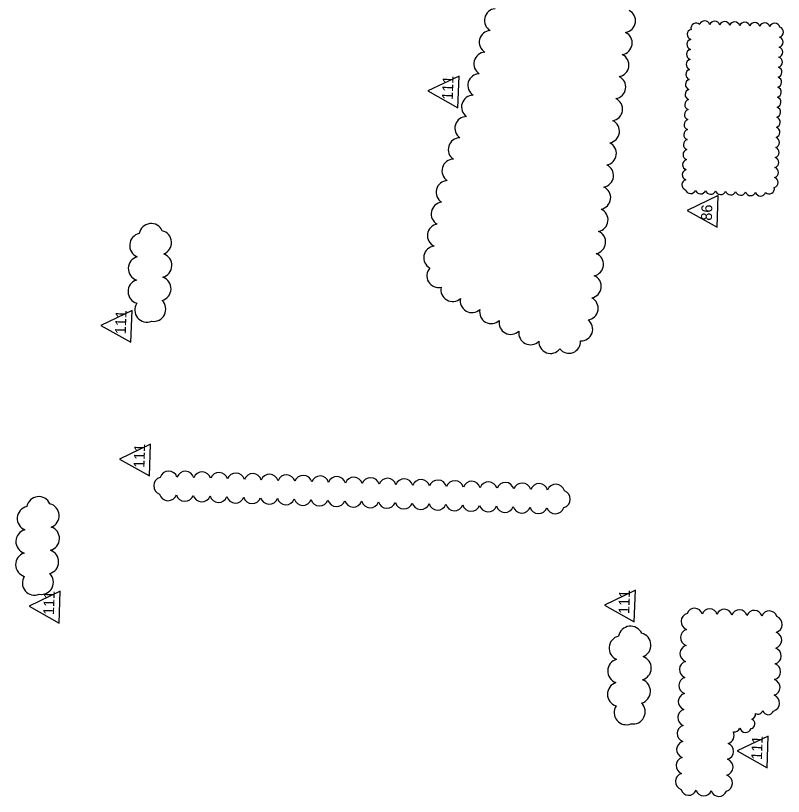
# Model space of a CAD drawing. Extents: x 928669 to 929521, y 636891 to 638153.
# Drawn here: x 928846 to 929187, y 637343.5 to 637690.4 of the extents above; entities that cross this region are included whole.
import ezdxf

# ---------------------------------------------------------------- set-up
doc = ezdxf.new("R2010")
doc.units = 0
doc.layers.add('Cloud_dp', color=7, linetype='Continuous')

msp = doc.modelspace()

# ---------------------------------------------------------------- linework, layer by layer
at = {"layer": 'Cloud_dp'}
for points in [[(929029.16, 637656.92), (929042.47, 637649.41), (929042.96, 637663.49)], [(929144.26, 637603.89), (929157.57, 637596.38), (929158.06, 637610.45)], [(928883.91, 637552.78), (928897.22, 637545.27), (928897.71, 637559.35)], [(928892.18, 637493.38), (928905.49, 637485.87), (928905.98, 637499.95)], [(928852.01, 637428.07), (928865.32, 637420.55), (928865.81, 637434.63)], [(929107.53, 637428.51), (929120.84, 637421), (929121.33, 637435.07)], [(929166.5, 637363.72), (929179.81, 637356.21), (929180.3, 637370.28)]]:
    msp.add_lwpolyline(points, close=True, dxfattribs=at)
for centre, radius, start, end in [((929059.45, 637688.27), 5.2, 94.6831, 239.6831), ((929116.19, 637688.07), 5.2, 278.7266, 63.7266), ((929148.31, 637684.8), 2.33, 47.7982, 192.7982), ((929152.08, 637685.75), 2.34, 15.4978, 160.4978), ((929156.53, 637685.59), 2.34, 15.4978, 160.4978), ((929160.99, 637685.43), 2.34, 15.4978, 160.4978), ((929165.44, 637685.28), 2.34, 15.4978, 160.4978), ((929169.89, 637685.12), 2.34, 15.4978, 160.4978), ((929174.34, 637684.97), 2.34, 15.4978, 160.4978), ((929178.79, 637684.81), 2.34, 15.4978, 160.4978), ((929183.24, 637684.66), 2.34, 15.4978, 160.4978), ((929184.71, 637683.08), 2.34, 285.4978, 70.4978), ((929057.16, 637678.6), 5.2, 93.763, 238.763), ((929114.7, 637678.26), 5.2, 278.9601, 63.9601), ((929146.66, 637682.03), 2.34, 105.4978, 250.4978), ((929146.51, 637677.58), 2.34, 105.4978, 250.4978), ((929184.56, 637678.63), 2.34, 285.4978, 70.4978), ((929146.35, 637673.13), 2.34, 105.4978, 250.4978), ((929184.4, 637674.18), 2.34, 285.4978, 70.4978), ((929054.72, 637668.97), 5.2, 92.7581, 237.7581), ((929113.24, 637668.45), 5.2, 279.1299, 64.1299), ((929184.25, 637669.73), 2.34, 285.4978, 70.4978), ((929146.2, 637668.68), 2.34, 105.4978, 250.4978), ((929052.1, 637659.38), 5.2, 91.6555, 236.6555), ((929146.04, 637664.22), 2.34, 105.4978, 250.4978), ((929184.09, 637665.28), 2.34, 285.4978, 70.4978), ((929111.81, 637658.64), 5.2, 279.2689, 64.2689), ((929145.88, 637659.77), 2.34, 105.4978, 250.4978), ((929183.93, 637660.82), 2.34, 285.4978, 70.4978), ((929145.73, 637655.32), 2.34, 105.4978, 250.4978), ((929183.78, 637656.37), 2.34, 285.4978, 70.4978), ((929049.28, 637649.85), 5.2, 90.4397, 235.4397), ((929183.62, 637651.92), 2.34, 285.4978, 70.4978), ((929110.4, 637648.83), 5.2, 279.426, 64.426), ((929145.57, 637650.87), 2.34, 105.4978, 250.4978), ((929145.42, 637646.42), 2.34, 105.4978, 250.4978), ((929183.47, 637647.47), 2.34, 285.4978, 70.4978), ((929046.32, 637640.37), 5.2, 89.8867, 234.8867), ((929109.03, 637639.01), 5.2, 279.6117, 64.6117), ((929145.26, 637641.97), 2.34, 105.4978, 250.4978), ((929183.31, 637643.02), 2.34, 285.4978, 70.4978), ((929183.16, 637638.57), 2.34, 285.4978, 70.4978), ((929145.11, 637637.52), 2.34, 105.4978, 250.4978), ((929043.39, 637630.93), 5.2, 90.5611, 235.5611), ((929107.68, 637629.19), 5.2, 279.8348, 64.8348), ((929144.95, 637633.07), 2.34, 105.4978, 250.4978), ((929183, 637634.12), 2.34, 285.4978, 70.4978), ((929144.8, 637628.62), 2.34, 105.4978, 250.4978), ((929182.84, 637629.67), 2.34, 285.4978, 70.4978), ((929040.59, 637621.45), 5.2, 91.5317, 236.5317), ((929144.64, 637624.16), 2.34, 105.4978, 250.4978), ((929182.69, 637625.21), 2.34, 285.4978, 70.4978), ((929106.39, 637619.35), 5.2, 280.11, 65.11), ((929182.53, 637620.76), 2.34, 285.4978, 70.4978), ((929144.48, 637619.71), 2.34, 105.4978, 250.4978), ((929038, 637611.92), 5.2, 93.0676, 238.0676), ((929144.33, 637615.26), 2.34, 105.4978, 250.4978), ((929182.38, 637616.31), 2.34, 285.4978, 70.4978), ((929105.14, 637609.51), 5.2, 280.4616, 65.4616), ((929145.8, 637613.69), 2.34, 195.4978, 340.4978), ((929150.25, 637613.53), 2.34, 195.4978, 340.4978), ((929154.7, 637613.37), 2.34, 195.4978, 340.4978), ((929159.15, 637613.22), 2.34, 195.4978, 340.4978), ((929163.6, 637613.06), 2.34, 195.4978, 340.4978), ((929180.73, 637613.55), 2.33, 227.7982, 12.7982), ((929168.05, 637612.91), 2.34, 195.4978, 340.4978), ((929172.51, 637612.75), 2.34, 195.4978, 340.4978), ((929176.96, 637612.6), 2.34, 195.4978, 340.4978), ((929035.8, 637602.35), 5.2, 96.0987, 241.0987), ((929103.96, 637599.66), 5.2, 280.9328, 65.9328), ((928906.22, 637592.6), 5.42, 24.5019, 169.5019), ((929034.14, 637592.67), 5.2, 99.3819, 244.3819), ((928902.08, 637588.29), 5.42, 102.6495, 247.6495), ((928909.85, 637589.58), 5.42, 291.0688, 76.0688), ((929102.89, 637589.79), 5.2, 281.6123, 66.6123), ((929032.48, 637582.83), 5.2, 96.4457, 241.4457), ((929101.94, 637579.9), 5.2, 282.473, 67.473), ((928901.48, 637578.05), 5.42, 105.565, 250.565), ((928909.99, 637579.4), 5.42, 285.576, 70.576), ((929033.87, 637574.8), 5.2, 138.1807, 283.1807), ((929100.96, 637570.08), 5.2, 281.1172, 66.1172), ((928901.36, 637567.78), 5.42, 108.172, 253.172), ((928909.64, 637569.07), 5.42, 285.4978, 70.4978), ((929040.12, 637568.62), 5.2, 167.5484, 312.5484), ((928907.29, 637559.97), 5.42, 260.4905, 45.4905), ((929048.71, 637563.67), 5.2, 167.5609, 312.5609), ((929099.58, 637560.36), 5.2, 277.71, 62.71), ((928904.35, 637559.65), 5.42, 147.1328, 292.1328), ((929057.31, 637558.77), 5.2, 168.0431, 313.0431), ((929065.95, 637553.98), 5.2, 169.0303, 314.0303), ((929097.14, 637551.07), 5.2, 267.8534, 52.8534), ((929074.69, 637549.41), 5.2, 170.7541, 315.7541), ((929083.6, 637545.52), 5.2, 176.9989, 321.9989), ((929091.76, 637545.56), 5.19, 218.5581, 3.5581), ((928913.97, 637484.12), 3.92, 18.2984, 163.2984), ((928921.39, 637484.05), 3.92, 15.4978, 160.4978), ((928928.87, 637483.79), 3.92, 15.4978, 160.4978), ((928911.26, 637481.47), 3.92, 105.4978, 250.4978), ((928936.36, 637483.52), 3.92, 15.4978, 160.4978), ((928943.84, 637483.26), 3.92, 15.4978, 160.4978), ((928951.32, 637483), 3.92, 15.4978, 160.4978), ((928958.8, 637482.74), 3.92, 15.4978, 160.4978), ((928966.28, 637482.48), 3.92, 15.4978, 160.4978), ((928973.76, 637482.22), 3.92, 15.4978, 160.4978), ((928981.24, 637481.95), 3.92, 15.4978, 160.4978), ((928988.73, 637481.69), 3.92, 15.4978, 160.4978), ((928996.21, 637481.43), 3.92, 15.4978, 160.4978), ((929003.69, 637481.17), 3.92, 15.4978, 160.4978), ((929011.17, 637480.91), 3.92, 15.4978, 160.4978), ((929018.65, 637480.65), 3.92, 15.4978, 160.4978), ((929026.13, 637480.39), 3.92, 15.4978, 160.4978), ((929033.61, 637480.12), 3.92, 15.4978, 160.4978), ((929041.1, 637479.86), 3.92, 15.4978, 160.4978), ((929048.58, 637479.6), 3.92, 15.4978, 160.4978), ((929056.06, 637479.34), 3.92, 15.4978, 160.4978), ((929063.54, 637479.08), 3.92, 15.4978, 160.4978), ((929071.02, 637478.82), 3.92, 15.4978, 160.4978), ((929078.5, 637478.55), 3.92, 15.4978, 160.4978), ((929085.98, 637478.29), 3.92, 15.4978, 160.4978), ((928913.73, 637478.82), 3.92, 195.4978, 340.4978), ((928921.21, 637478.56), 3.92, 195.4978, 340.4978), ((928928.69, 637478.3), 3.92, 195.4978, 340.4978), ((929088.46, 637475.64), 3.92, 285.4978, 70.4978), ((928856.3, 637471.27), 5.42, 24.5019, 169.5019), ((928936.17, 637478.04), 3.92, 195.4978, 340.4978), ((928943.66, 637477.77), 3.92, 195.4978, 340.4978), ((928951.14, 637477.51), 3.92, 195.4978, 340.4978), ((928958.62, 637477.25), 3.92, 195.4978, 340.4978), ((928966.1, 637476.99), 3.92, 195.4978, 340.4978), ((928973.58, 637476.73), 3.92, 195.4978, 340.4978), ((928981.06, 637476.47), 3.92, 195.4978, 340.4978), ((928988.54, 637476.2), 3.92, 195.4978, 340.4978), ((928996.03, 637475.94), 3.92, 195.4978, 340.4978), ((929003.51, 637475.68), 3.92, 195.4978, 340.4978), ((929010.99, 637475.42), 3.92, 195.4978, 340.4978), ((929018.47, 637475.16), 3.92, 195.4978, 340.4978), ((929025.95, 637474.9), 3.92, 195.4978, 340.4978), ((928852.16, 637466.97), 5.42, 102.6495, 247.6495), ((928859.92, 637468.25), 5.42, 291.0688, 76.0688), ((929033.43, 637474.64), 3.92, 195.4978, 340.4978), ((929040.91, 637474.37), 3.92, 195.4978, 340.4978), ((929048.4, 637474.11), 3.92, 195.4978, 340.4978), ((929055.88, 637473.85), 3.92, 195.4978, 340.4978), ((929063.36, 637473.59), 3.92, 195.4978, 340.4978), ((929070.84, 637473.33), 3.92, 195.4978, 340.4978), ((929078.32, 637473.07), 3.92, 195.4978, 340.4978), ((929085.75, 637472.99), 3.92, 198.2984, 343.2984), ((928851.55, 637456.73), 5.42, 105.565, 250.565), ((928860.07, 637458.08), 5.42, 285.576, 70.576), ((928859.71, 637447.74), 5.42, 285.4978, 70.4978), ((928851.44, 637446.46), 5.42, 108.172, 253.172), ((928857.36, 637438.65), 5.42, 260.4905, 45.4905), ((928854.42, 637438.32), 5.42, 147.1328, 292.1328), ((929147.6, 637423.63), 3.48, 15.4978, 160.4978), ((929154.24, 637423.39), 3.48, 15.4978, 160.4978), ((929160.87, 637423.16), 3.48, 15.4978, 160.4978), ((929167.5, 637422.93), 3.48, 15.4978, 160.4978), ((929174.13, 637422.7), 3.48, 15.4978, 160.4978), ((929180.76, 637422.47), 3.48, 15.4978, 160.4978), ((929145.32, 637421.19), 3.73, 105.4978, 250.4978), ((929182.89, 637419.94), 3.67, 285.4978, 70.4978), ((929119.17, 637413.73), 5.42, 24.5019, 169.5019), ((929115.04, 637409.43), 5.42, 102.6495, 247.6495), ((929122.8, 637410.72), 5.42, 291.0688, 76.0688), ((929145.07, 637414.08), 3.73, 105.4978, 250.4978), ((929182.65, 637412.95), 3.67, 285.4978, 70.4978), ((929144.82, 637406.97), 3.73, 105.4978, 250.4978), ((929182.4, 637405.95), 3.67, 285.4978, 70.4978), ((929114.43, 637399.19), 5.42, 105.565, 250.565), ((929122.94, 637400.54), 5.42, 285.576, 70.576), ((929144.58, 637399.86), 3.73, 105.4978, 250.4978), ((929182.16, 637398.96), 3.67, 285.4978, 70.4978), ((929114.32, 637388.92), 5.42, 108.172, 253.172), ((929122.59, 637390.21), 5.42, 285.4978, 70.4978), ((929144.33, 637392.75), 3.73, 105.4978, 250.4978), ((929181.91, 637391.97), 3.67, 285.4978, 70.4978), ((929144.08, 637385.64), 3.73, 105.4978, 250.4978), ((929181.67, 637384.97), 3.67, 285.4978, 70.4978), ((929117.3, 637380.79), 5.42, 147.1328, 292.1328), ((929120.24, 637381.11), 5.42, 260.4905, 45.4905), ((929143.83, 637378.53), 3.73, 105.4978, 250.4978), ((929172.45, 637379.88), 2.18, 284.5394, 10.7447), ((929175.61, 637382.55), 2.48, 245.7447, 339.5394), ((929180.33, 637382.3), 2.48, 194.5394, 339.5394), ((929172.23, 637375.73), 2.18, 284.5394, 69.5394), ((929143.58, 637371.42), 3.73, 105.4978, 250.4978), ((929165.26, 637374.8), 2.65, 260.639, 339.5394), ((929170.3, 637374.54), 2.65, 194.5394, 339.5394), ((929161.46, 637370.64), 3.71, 285.4978, 24.6806), ((929143.33, 637364.31), 3.73, 105.4978, 250.4978), ((929161.21, 637363.57), 3.71, 285.4978, 70.4978), ((929143.08, 637357.2), 3.73, 105.4978, 250.4978), ((929160.97, 637356.51), 3.71, 285.4978, 70.4978), ((929142.84, 637350.09), 3.73, 105.4978, 250.4978), ((929160.72, 637349.44), 3.71, 285.4978, 70.4978), ((929144.98, 637347.51), 3.52, 195.4978, 340.4978), ((929151.69, 637347.28), 3.52, 195.4978, 340.4978), ((929158.39, 637347.04), 3.52, 195.4978, 340.4978)]:
    msp.add_arc(centre, radius, start, end, dxfattribs=at)

# ---------------------------------------------------------------- texts
for s, p in [('111', (929040.18, 637652.9)), ('86', (929155.25, 637599.24)), ('111', (928894.93, 637548.76)), ('111', (928903.2, 637489.36)), ('111', (928863.03, 637424.05)), ('111', (929118.55, 637424.49)), ('111', (929177.52, 637359.7))]:
    msp.add_text(s, height=4.8, rotation=87.9978, dxfattribs=at).set_placement(p)

doc.saveas('drawing.dxf')
